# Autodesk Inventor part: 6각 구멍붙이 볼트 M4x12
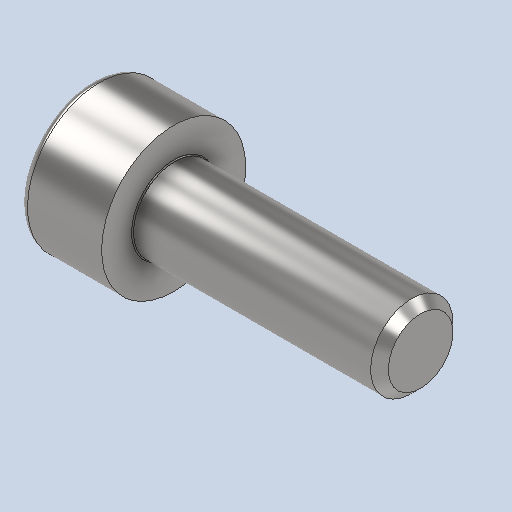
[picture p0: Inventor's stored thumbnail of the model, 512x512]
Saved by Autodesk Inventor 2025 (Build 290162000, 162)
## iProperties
Created: 2026-04
Part Number: 6각 구멍붙이 볼트 M4x12
Material: 강철, 연강
Description: 6각머리 태핑 나사
Document SubType Name: Modeling
Designer: KDI
Density: 7.85 g/cm^3
Appearance: 기본값
Sending System: Autodesk Inventor 2027
Preprocessor: ST-DEVELOPER v20.1
Author: jhkim
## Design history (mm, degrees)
feature "Solid1"
node "솔리드1"
